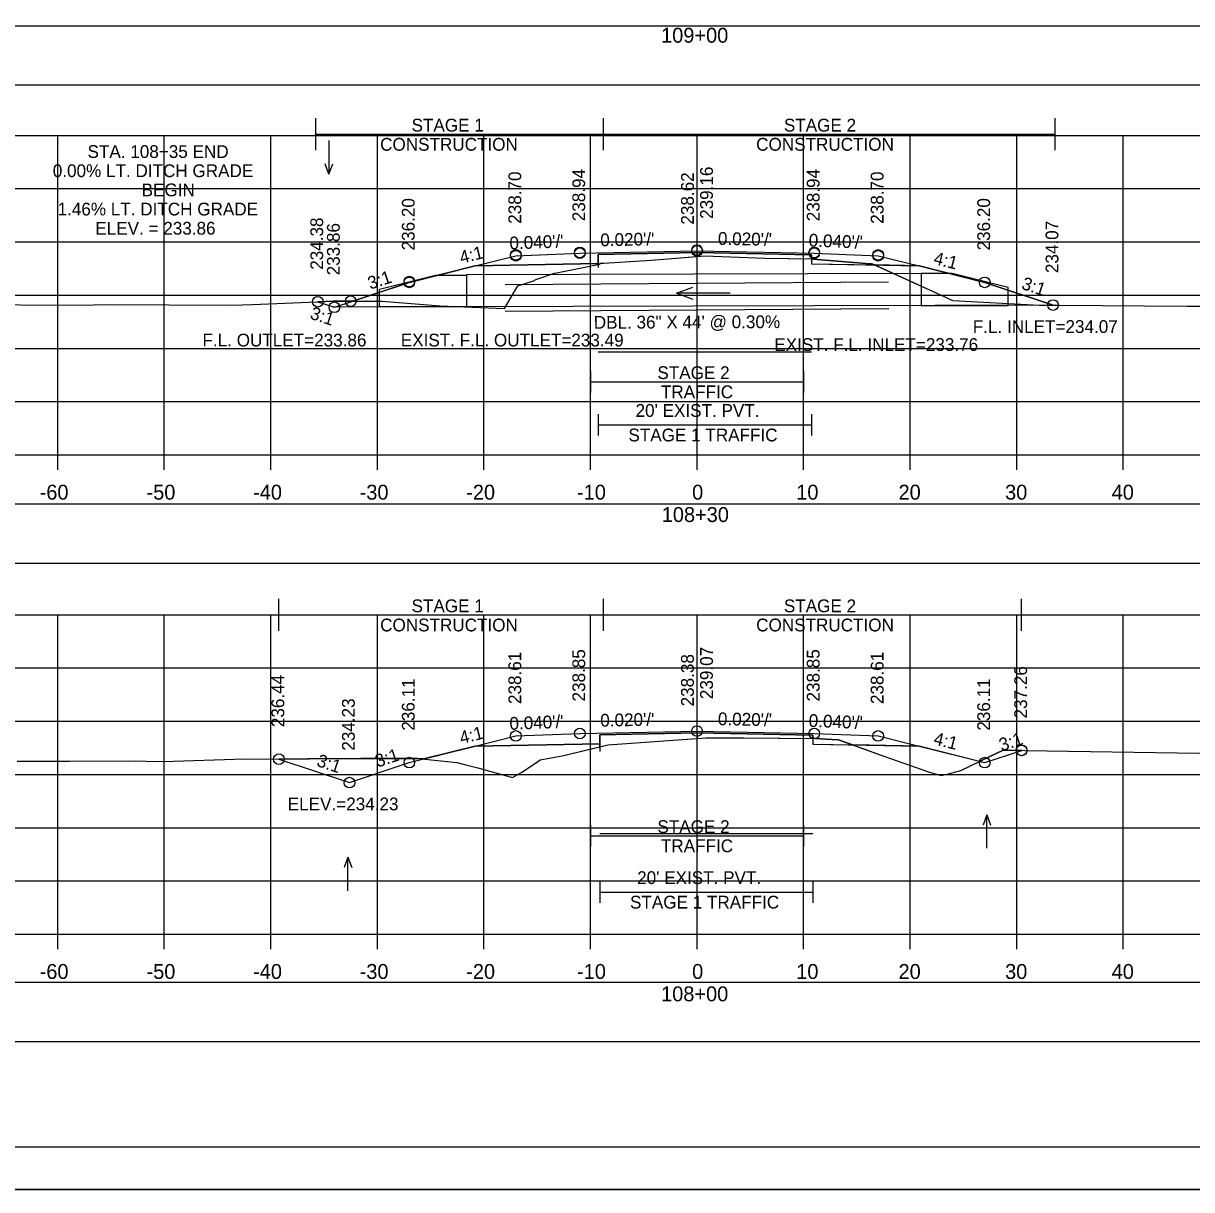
# Model space of a CAD drawing. Extents: x 1369627 to 1374022, y 380035 to 398173.
# Drawn here: x 1370116 to 1370225.7, y 380674.9 to 380784.4 of the extents above; entities that cross this region are included whole.
import ezdxf

# ---------------------------------------------------------------- set-up
doc = ezdxf.new("R2010")
doc.units = 0
for name, color, linetype in [('Default', 7, 'Continuous'), ('R_Alt Surface', 7, 'Continuous'), ('R_Axis', 7, 'Continuous'), ('R_Axis Annot', 7, 'Continuous'), ('R_Border', 7, 'Continuous'), ('R_Border Notes', 7, 'Continuous'), ('R_Exist Surface', 7, 'Continuous'), ('R_Fin Surface', 7, 'Continuous'), ('R_Grid', 7, 'Continuous'), ('R_MOT', 7, 'Continuous'), ('R_No Plot', 7, 'Continuous'), ('R_Water', 7, 'Continuous'), ('R_Water Annot', 7, 'Continuous'), ('R_Xsect Elev', 7, 'Continuous'), ('R_Xsect Slope', 7, 'Continuous'), ('T_Vehicle Path Rt', 7, 'Continuous')]:
    doc.layers.add(name, color=color, linetype=linetype)

msp = doc.modelspace()

# ---------------------------------------------------------------- linework, layer by layer
at = {"layer": 'Default'}
for points in [[(1370029.24, 380778.6), (1370329.24, 380778.6), (1370329.24, 380784.12), (1370029.24, 380784.12)], [(1370029.24, 380733.71), (1370329.24, 380733.71), (1370329.24, 380739.23), (1370029.24, 380739.23)], [(1370029.24, 380688.8), (1370329.24, 380688.8), (1370329.24, 380694.33), (1370029.24, 380694.33)]]:
    msp.add_lwpolyline(points, close=True, dxfattribs=at)
at = {"layer": 'R_Alt Surface'}
for points in [[(1370158.41, 380761.62), (1370169.97, 380761.85), (1370169.97, 380762.68), (1370179.24, 380762.87), (1370189.97, 380762.65), (1370189.97, 380761.82), (1370200.07, 380761.62)], [(1370158.41, 380716.52), (1370170.11, 380716.75), (1370170.11, 380717.59), (1370179.24, 380717.77), (1370190.11, 380717.55), (1370190.11, 380716.72), (1370200.07, 380716.52)]]:
    msp.add_lwpolyline(points, dxfattribs=at)
at = {"layer": 'R_Axis'}
for p, q in [((1370029.24, 380743.87), (1370329.24, 380743.87)), ((1370119.24, 380742.47), (1370119.24, 380743.87)), ((1370129.24, 380742.47), (1370129.24, 380743.87)), ((1370139.24, 380742.47), (1370139.24, 380743.87)), ((1370149.24, 380742.47), (1370149.24, 380743.87)), ((1370159.24, 380742.47), (1370159.24, 380743.87)), ((1370169.24, 380742.47), (1370169.24, 380743.87)), ((1370179.24, 380742.47), (1370179.24, 380743.87)), ((1370189.24, 380742.47), (1370189.24, 380743.87)), ((1370199.24, 380742.47), (1370199.24, 380743.87)), ((1370209.24, 380742.47), (1370209.24, 380743.87)), ((1370219.24, 380742.47), (1370219.24, 380743.87)), ((1370029.24, 380698.87), (1370329.24, 380698.87)), ((1370119.24, 380697.47), (1370119.24, 380698.87)), ((1370129.24, 380697.47), (1370129.24, 380698.87)), ((1370139.24, 380697.47), (1370139.24, 380698.87)), ((1370149.24, 380697.47), (1370149.24, 380698.87)), ((1370159.24, 380697.47), (1370159.24, 380698.87)), ((1370169.24, 380697.47), (1370169.24, 380698.87)), ((1370179.24, 380697.47), (1370179.24, 380698.87)), ((1370189.24, 380697.47), (1370189.24, 380698.87)), ((1370199.24, 380697.47), (1370199.24, 380698.87)), ((1370209.24, 380697.47), (1370209.24, 380698.87)), ((1370219.24, 380697.47), (1370219.24, 380698.87))]:
    msp.add_line(p, q, dxfattribs=at)
at = {"layer": 'R_Border'}
msp.add_line((1370337.42, 380678.87), (1370021.24, 380678.87), dxfattribs=at)
at = {"layer": 'R_Exist Surface'}
for points in [[(1370110.13, 380757.98), (1370121.37, 380757.94), (1370123.82, 380757.99), (1370135.59, 380757.94), (1370137.53, 380757.98), (1370145.1, 380758.31), (1370149.7, 380758.3), (1370155.13, 380757.88), (1370161.16, 380757.62), (1370162.42, 380759.73), (1370163.88, 380760.21), (1370164.11, 380760.35), (1370165.85, 380760.92), (1370165.88, 380760.93), (1370165.89, 380760.93), (1370165.9, 380760.93), (1370170.13, 380761.78), (1370170.18, 380761.87), (1370170.5, 380761.88), (1370174.95, 380762.14), (1370179.97, 380762.55), (1370185.6, 380762.35), (1370190.11, 380762.27), (1370190.12, 380762.26), (1370190.14, 380762.26), (1370195.46, 380761.82), (1370195.6, 380761.8), (1370195.74, 380761.78), (1370202.48, 380758.71), (1370203.21, 380758.38), (1370211.37, 380757.93), (1370213.26, 380757.94), (1370225.23, 380757.84), (1370226.95, 380757.83)], [(1370115.45, 380715.13), (1370120.35, 380715.13), (1370125.88, 380715.15), (1370129.14, 380715.09), (1370136.79, 380715.35), (1370139.23, 380715.3), (1370142.78, 380715.33), (1370142.81, 380715.33), (1370142.85, 380715.33), (1370147.69, 380715.36), (1370151.87, 380715.37), (1370153, 380715.38), (1370153.71, 380715.31), (1370156.7, 380714.99), (1370157.53, 380714.77), (1370158.67, 380714.48), (1370161.91, 380713.59), (1370162.8, 380714.08), (1370164.07, 380714.93), (1370164.52, 380715.24), (1370166.58, 380715.63), (1370170.87, 380716.64), (1370177.01, 380717.1), (1370180.11, 380717.32), (1370183.63, 380717.3), (1370190.4, 380717.25), (1370191.32, 380717.19), (1370192.51, 380717.13), (1370196.76, 380715.59), (1370200.96, 380714.13), (1370201.5, 380713.97), (1370202.15, 380713.76), (1370203.06, 380714), (1370204, 380714.23), (1370205.93, 380715.18), (1370207.97, 380716.16), (1370232.51, 380715.78)]]:
    msp.add_lwpolyline(points, dxfattribs=at)
at = {"layer": 'R_Fin Surface'}
for points in [[(1370143.65, 380758.25), (1370145.21, 380757.73), (1370152.24, 380760.07), (1370158.41, 380761.62), (1370162.24, 380762.57), (1370168.24, 380762.81), (1370179.24, 380763.03), (1370190.24, 380762.81), (1370196.24, 380762.57), (1370200.07, 380761.62), (1370206.24, 380760.07), (1370212.65, 380757.94)], [(1370140, 380715.31), (1370146.62, 380713.1), (1370152.24, 380714.98), (1370158.41, 380716.52), (1370162.24, 380717.48), (1370168.24, 380717.72), (1370179.24, 380717.94), (1370190.24, 380717.72), (1370196.24, 380717.48), (1370200.07, 380716.52), (1370206.24, 380714.98), (1370209.71, 380716.13)]]:
    msp.add_lwpolyline(points, dxfattribs=at)
at = {"layer": 'R_Grid'}
for p, q in [((1370029.24, 380773.87), (1370329.24, 380773.87)), ((1370119.24, 380743.87), (1370119.24, 380773.87)), ((1370129.24, 380743.87), (1370129.24, 380773.87)), ((1370139.24, 380743.87), (1370139.24, 380773.87)), ((1370149.24, 380743.87), (1370149.24, 380773.87)), ((1370159.24, 380743.87), (1370159.24, 380773.87)), ((1370169.24, 380743.87), (1370169.24, 380773.87)), ((1370179.24, 380743.87), (1370179.24, 380773.87)), ((1370189.24, 380743.87), (1370189.24, 380773.87)), ((1370199.24, 380743.87), (1370199.24, 380773.87)), ((1370209.24, 380743.87), (1370209.24, 380773.87)), ((1370219.24, 380743.87), (1370219.24, 380773.87)), ((1370029.24, 380768.87), (1370329.24, 380768.87)), ((1370029.24, 380763.87), (1370329.24, 380763.87)), ((1370029.24, 380758.87), (1370329.24, 380758.87)), ((1370029.24, 380753.87), (1370329.24, 380753.87)), ((1370029.24, 380748.87), (1370329.24, 380748.87)), ((1370029.24, 380743.87), (1370329.24, 380743.87)), ((1370029.24, 380728.87), (1370329.24, 380728.87)), ((1370119.24, 380698.87), (1370119.24, 380728.87)), ((1370129.24, 380698.87), (1370129.24, 380728.87)), ((1370139.24, 380698.87), (1370139.24, 380728.87)), ((1370149.24, 380698.87), (1370149.24, 380728.87)), ((1370159.24, 380698.87), (1370159.24, 380728.87)), ((1370169.24, 380698.87), (1370169.24, 380728.87)), ((1370179.24, 380698.87), (1370179.24, 380728.87)), ((1370189.24, 380698.87), (1370189.24, 380728.87)), ((1370199.24, 380698.87), (1370199.24, 380728.87)), ((1370209.24, 380698.87), (1370209.24, 380728.87)), ((1370219.24, 380698.87), (1370219.24, 380728.87)), ((1370029.24, 380723.87), (1370329.24, 380723.87)), ((1370029.24, 380718.87), (1370329.24, 380718.87)), ((1370029.24, 380713.87), (1370329.24, 380713.87)), ((1370029.24, 380708.87), (1370329.24, 380708.87)), ((1370029.24, 380703.87), (1370329.24, 380703.87)), ((1370029.24, 380698.87), (1370329.24, 380698.87))]:
    msp.add_line(p, q, dxfattribs=at)
at = {"layer": 'R_MOT'}
for p, q in [((1370143.47, 380772.48), (1370143.47, 380775.48)), ((1370170.47, 380772.48), (1370170.47, 380775.48)), ((1370212.86, 380772.48), (1370212.86, 380775.48)), ((1370143.47, 380773.98), (1370212.86, 380773.98)), ((1370169.24, 380751.72), (1370169.24, 380749.72)), ((1370189.24, 380751.72), (1370189.24, 380749.72)), ((1370169.24, 380750.72), (1370189.24, 380750.72)), ((1370169.97, 380747.68), (1370169.97, 380745.68)), ((1370189.97, 380747.68), (1370189.97, 380745.68)), ((1370169.97, 380746.68), (1370189.97, 380746.68)), ((1370139.99, 380727.35), (1370139.99, 380730.35)), ((1370170.47, 380727.35), (1370170.47, 380730.35)), ((1370209.69, 380727.35), (1370209.69, 380730.35)), ((1370139.99, 380728.85), (1370209.69, 380728.85)), ((1370169.24, 380709.1), (1370169.24, 380707.1)), ((1370189.24, 380709.1), (1370189.24, 380707.1)), ((1370169.24, 380708.1), (1370189.24, 380708.1)), ((1370170.11, 380703.82), (1370170.11, 380701.82)), ((1370190.11, 380703.82), (1370190.11, 380701.82)), ((1370170.11, 380702.82), (1370190.11, 380702.82))]:
    msp.add_line(p, q, dxfattribs=at)
at = {"layer": 'R_No Plot'}
msp.add_line((1370008.84, 380674.89), (1370342.17, 380674.89), dxfattribs=at)
for points in [[(1370008.83, 380888.23), (1370342.17, 380888.23), (1370342.17, 380674.89), (1370008.83, 380674.89)], [(1370255.16, 380884.33), (1370274.78, 380884.33), (1370274.78, 380874.45), (1370290.89, 380874.45), (1370314.09, 380874.45), (1370314.09, 380841.78), (1370337.3, 380841.78), (1370337.42, 380678.87), (1370021.24, 380678.87), (1370021.24, 380884.33)]]:
    msp.add_lwpolyline(points, close=True, dxfattribs=at)
for points in [[(1370169.97, 380753.55), (1370189.97, 380753.55)], [(1370170.11, 380708.32), (1370190.11, 380708.32)]]:
    msp.add_lwpolyline(points, dxfattribs=at)
for centre in [(1370168.24, 380762.88), (1370168.24, 380762.81), (1370179.24, 380763.1), (1370179.24, 380763.03), (1370190.24, 380762.88), (1370190.24, 380762.81), (1370162.24, 380762.64), (1370162.24, 380762.57), (1370196.24, 380762.64), (1370196.24, 380762.57), (1370152.24, 380760.14), (1370152.24, 380760.07), (1370206.24, 380760.07), (1370143.65, 380758.25), (1370145.21, 380757.73), (1370146.74, 380758.31), (1370212.65, 380757.94), (1370179.24, 380717.94), (1370162.24, 380717.48), (1370168.24, 380717.72), (1370190.24, 380717.72), (1370196.24, 380717.48), (1370196.24, 380717.48), (1370209.69, 380716.13), (1370209.71, 380716.13), (1370140, 380715.31), (1370152.24, 380714.98), (1370206.24, 380714.98), (1370146.62, 380713.1)]:
    msp.add_circle(centre, 0.5, dxfattribs=at)
at = {"layer": 'R_Water'}
for p, q in [((1370200.28, 380760.9), (1370157.6, 380760.77)), ((1370161.22, 380759.86), (1370197.22, 380760.13)), ((1370212.86, 380757.94), (1370145, 380757.73)), ((1370161.24, 380757.36), (1370197.24, 380757.63))]:
    msp.add_line(p, q, dxfattribs=at)
for points in [[(1370157.6, 380760.76), (1370157.6, 380757.76), (1370149.45, 380757.76), (1370149.45, 380759.43), (1370154.7, 380760.76)], [(1370200.28, 380760.91), (1370200.28, 380757.91), (1370208.43, 380757.91), (1370208.43, 380759.58), (1370203.18, 380760.91)]]:
    msp.add_lwpolyline(points, close=True, dxfattribs=at)
at = {"layer": 'R_Water Annot'}
for p, q in [((1370144.7, 380773.38), (1370144.7, 380770.24)), ((1370144.7, 380770.24), (1370144.35, 380771.2)), ((1370144.7, 380770.24), (1370145.05, 380771.2)), ((1370177.31, 380759.05), (1370178.85, 380759.61)), ((1370182.34, 380759.05), (1370177.31, 380759.05)), ((1370177.31, 380759.05), (1370178.85, 380758.49)), ((1370206.43, 380710.08), (1370206.08, 380709.12)), ((1370206.43, 380706.94), (1370206.43, 380710.08)), ((1370206.43, 380710.08), (1370206.78, 380709.12)), ((1370146.48, 380706.09), (1370146.13, 380705.13)), ((1370146.48, 380702.95), (1370146.48, 380706.09)), ((1370146.48, 380706.09), (1370146.83, 380705.13))]:
    msp.add_line(p, q, dxfattribs=at)
at = {"layer": 'R_Xsect Elev'}
for p, q in [((1370179.24, 380762.49), (1370179.24, 380772.49)), ((1370179.24, 380717.26), (1370179.24, 380727.26))]:
    msp.add_line(p, q, dxfattribs=at)
at = {"layer": 'T_Vehicle Path Rt'}
for p, q in [((1370179.24, 380762.49), (1370179.24, 380762.87)), ((1370189.97, 380762.65), (1370179.24, 380762.87)), ((1370179.24, 380762.87), (1370179.24, 380762.49)), ((1370189.97, 380762.27), (1370189.97, 380762.65)), ((1370189.97, 380762.27), (1370189.97, 380761.82)), ((1370169.97, 380761.85), (1370158.41, 380761.62)), ((1370169.97, 380761.85), (1370169.97, 380761.45)), ((1370169.97, 380761.75), (1370169.97, 380761.85)), ((1370169.97, 380761.85), (1370169.97, 380761.75)), ((1370189.97, 380761.82), (1370195.92, 380761.7)), ((1370200.07, 380761.62), (1370195.92, 380761.7)), ((1370195.92, 380761.7), (1370202.48, 380758.71)), ((1370145.1, 380758.31), (1370143.65, 380758.25)), ((1370146.94, 380758.31), (1370145.1, 380758.31)), ((1370190.11, 380717.55), (1370179.24, 380717.77)), ((1370179.24, 380717.77), (1370179.24, 380717.26)), ((1370179.24, 380717.26), (1370179.24, 380717.77)), ((1370190.11, 380717.26), (1370190.11, 380717.55)), ((1370158.41, 380716.52), (1370153.61, 380715.32)), ((1370170.11, 380716.75), (1370158.41, 380716.52)), ((1370170.11, 380716.75), (1370170.11, 380716.01)), ((1370170.11, 380716.46), (1370170.11, 380716.75)), ((1370170.11, 380716.75), (1370170.11, 380716.46)), ((1370170.11, 380716.46), (1370170.87, 380716.64)), ((1370190.24, 380716.72), (1370193.83, 380716.65)), ((1370200.07, 380716.52), (1370193.86, 380716.64)), ((1370205.76, 380715.1), (1370200.07, 380716.52)), ((1370206.24, 380714.98), (1370209.71, 380716.13)), ((1370153.59, 380715.32), (1370153, 380715.38)), ((1370205.76, 380715.1), (1370206.24, 380714.98))]:
    msp.add_line(p, q, dxfattribs=at)
for points in [[(1370179.24, 380762.87), (1370169.97, 380762.68), (1370169.97, 380761.85)], [(1370169.97, 380761.75), (1370170.13, 380761.78), (1370170.18, 380761.87), (1370170.5, 380761.88), (1370174.95, 380762.14), (1370179.24, 380762.49)], [(1370179.24, 380762.49), (1370179.97, 380762.55), (1370185.6, 380762.35), (1370189.97, 380762.27)], [(1370195.92, 380761.7), (1370195.74, 380761.78), (1370195.6, 380761.8), (1370195.46, 380761.82), (1370190.14, 380762.26), (1370190.12, 380762.26), (1370190.11, 380762.27), (1370189.97, 380762.27)], [(1370146.94, 380758.31), (1370149.7, 380758.3), (1370155.13, 380757.88), (1370161.16, 380757.62), (1370162.42, 380759.73), (1370163.88, 380760.21), (1370164.11, 380760.35), (1370165.85, 380760.92), (1370165.88, 380760.93), (1370165.9, 380760.93), (1370169.97, 380761.75)], [(1370158.41, 380761.62), (1370152.24, 380760.07), (1370146.94, 380758.31)], [(1370212.65, 380757.94), (1370206.24, 380760.07), (1370200.07, 380761.62)], [(1370143.65, 380758.25), (1370145.21, 380757.73), (1370146.94, 380758.31)], [(1370202.48, 380758.71), (1370203.21, 380758.38), (1370211.37, 380757.93), (1370212.65, 380757.94)], [(1370179.24, 380717.77), (1370170.11, 380717.59), (1370170.11, 380716.75)], [(1370170.87, 380716.64), (1370177.01, 380717.1), (1370179.24, 380717.26)], [(1370179.24, 380717.26), (1370180.11, 380717.32), (1370183.63, 380717.3), (1370190.11, 380717.26)], [(1370190.24, 380717.26), (1370190.11, 380717.26), (1370190.11, 380716.72), (1370190.24, 380716.72)], [(1370193.83, 380716.65), (1370192.51, 380717.13), (1370191.32, 380717.19), (1370190.4, 380717.25), (1370190.24, 380717.26)], [(1370153.61, 380715.32), (1370153.71, 380715.31), (1370156.7, 380714.99), (1370157.53, 380714.77), (1370158.67, 380714.48), (1370161.91, 380713.59), (1370162.8, 380714.08), (1370164.07, 380714.93), (1370164.52, 380715.24), (1370166.58, 380715.63), (1370170.11, 380716.46)], [(1370193.86, 380716.64), (1370196.76, 380715.59), (1370200.96, 380714.13), (1370201.5, 380713.97), (1370202.15, 380713.76), (1370203.06, 380714), (1370204, 380714.23), (1370205.76, 380715.1)], [(1370209.71, 380716.13), (1370207.97, 380716.16), (1370205.93, 380715.18), (1370205.76, 380715.1)], [(1370153, 380715.38), (1370151.87, 380715.37), (1370147.69, 380715.36), (1370142.85, 380715.33), (1370142.81, 380715.33), (1370142.78, 380715.33), (1370140, 380715.31)], [(1370140, 380715.31), (1370146.62, 380713.1), (1370152.24, 380714.98), (1370153.6, 380715.32)], [(1370153.6, 380715.32), (1370153.59, 380715.32)], [(1370205.76, 380715.1), (1370205.76, 380715.1)]]:
    msp.add_lwpolyline(points, dxfattribs=at)

# ---------------------------------------------------------------- texts
at = {"layer": 'R_Axis Annot'}
for s, height, p in [('109+00', 1.4, (1370175.87, 380782.57)), ("20' EXIST. PVT.", 1.2, (1370173.47, 380747.44)), ('-60', 1.4, (1370117.55, 380739.67)), ('-50', 1.4, (1370127.58, 380739.67)), ('-40', 1.4, (1370137.58, 380739.67)), ('-30', 1.4, (1370147.58, 380739.67)), ('-20', 1.4, (1370157.58, 380739.67)), ('-10', 1.4, (1370167.98, 380739.67)), ('0', 1.4, (1370178.78, 380739.67)), ('10', 1.4, (1370188.55, 380739.67)), ('20', 1.4, (1370198.15, 380739.67)), ('30', 1.4, (1370208.15, 380739.67)), ('40', 1.4, (1370218.15, 380739.67)), ('108+30', 1.4, (1370175.93, 380737.57)), ("20' EXIST. PVT.", 1.2, (1370173.62, 380703.58)), ('-60', 1.4, (1370117.55, 380694.67)), ('-50', 1.4, (1370127.58, 380694.67)), ('-40', 1.4, (1370137.58, 380694.67)), ('-30', 1.4, (1370147.58, 380694.67)), ('-20', 1.4, (1370157.58, 380694.67)), ('-10', 1.4, (1370167.98, 380694.67)), ('0', 1.4, (1370178.78, 380694.67)), ('10', 1.4, (1370188.55, 380694.67)), ('20', 1.4, (1370198.15, 380694.67)), ('30', 1.4, (1370208.15, 380694.67)), ('40', 1.4, (1370218.15, 380694.67)), ('108+00', 1.4, (1370175.87, 380692.57))]:
    msp.add_text(s, height=height, dxfattribs=at).set_placement(p)
at = {"layer": 'R_Border Notes'}
for s, p in [('F.L. INLET=234.07', (1370205.12, 380755.32)), ('F.L. OUTLET=233.86', (1370132.83, 380754.05)), ('EXIST. F.L. OUTLET=233.49', (1370151.44, 380754.05)), ('EXIST. F.L. INLET=233.76', (1370186.49, 380753.63)), ('ELEV.=234.23', (1370140.83, 380710.5))]:
    msp.add_text(s, height=1.2, dxfattribs=at).set_placement(p)
at = {"layer": 'R_MOT'}
for s, p in [('STAGE 1', (1370152.45, 380774.23)), ('STAGE 2', (1370187.39, 380774.23)), ('CONSTRUCTION', (1370149.5, 380772.43)), ('CONSTRUCTION', (1370184.79, 380772.43)), ('STAGE 2', (1370175.52, 380750.99)), ('TRAFFIC', (1370175.85, 380749.19)), ('STAGE 1 TRAFFIC', (1370172.8, 380745.14)), ('STAGE 1', (1370152.45, 380729.1)), ('STAGE 2', (1370187.39, 380729.1)), ('CONSTRUCTION', (1370149.5, 380727.3)), ('CONSTRUCTION', (1370184.79, 380727.3)), ('STAGE 2', (1370175.52, 380708.37)), ('TRAFFIC', (1370175.85, 380706.57)), ('STAGE 1 TRAFFIC', (1370172.95, 380701.28))]:
    msp.add_text(s, height=1.2, dxfattribs=at).set_placement(p)
at = {"layer": 'R_Water Annot'}
msp.add_text('DBL. 36" X 44\' @ 0.30%', height=1.2, rotation=0.1754, dxfattribs=at).set_placement((1370169.55, 380755.72))
at = {"layer": 'R_Xsect Elev'}
for s, p in [('STA. 108+35 END', (1370122.04, 380771.75)), ('0.00% LT. DITCH GRADE', (1370118.78, 380769.95)), ('BEGIN', (1370127.12, 380768.15)), ('1.46% LT. DITCH GRADE', (1370119.23, 380766.35)), ('ELEV. = 233.86', (1370122.77, 380764.55))]:
    msp.add_text(s, height=1.2, dxfattribs=at).set_placement(p)
for s, p in [('238.70', (1370162.74, 380765.57)), ('238.94', (1370168.74, 380765.81)), ('238.62', (1370178.94, 380765.49)), ('239.16', (1370180.73, 380766.03)), ('238.94', (1370190.74, 380765.81)), ('238.70', (1370196.74, 380765.57)), ('236.20', (1370152.74, 380763.07)), ('236.20', (1370206.74, 380763.07)), ('234.38', (1370144.15, 380761.25)), ('233.86', (1370145.71, 380760.73)), ('234.07', (1370213.15, 380760.94)), ('238.61', (1370162.74, 380720.48)), ('238.85', (1370168.74, 380720.72)), ('238.38', (1370178.94, 380720.26)), ('239.07', (1370180.73, 380720.94)), ('238.85', (1370190.74, 380720.72)), ('238.61', (1370196.74, 380720.48)), ('237.26', (1370210.21, 380719.13)), ('236.44', (1370140.5, 380718.31)), ('236.11', (1370152.74, 380717.98)), ('236.11', (1370206.74, 380717.98)), ('234.23', (1370147.12, 380716.1))]:
    msp.add_text(s, height=1.2, rotation=90, dxfattribs=at).set_placement(p)
at = {"layer": 'R_Xsect Slope'}
for s, rotation, p in [("0.040'/'", 2.2906, (1370161.66, 380763.15)), ("0.020'/'", 1.1458, (1370170.17, 380763.45)), ("0.020'/'", 358.8542, (1370181.19, 380763.6)), ("0.040'/'", 357.7094, (1370189.7, 380763.44)), ('4:1', 14.0362, (1370157.12, 380761.81)), ('4:1', 345.9638, (1370201.36, 380761.81)), ('3:1', 18.4349, (1370148.57, 380759.38)), ('3:1', 341.5651, (1370209.61, 380759.48)), ('3:1', 341.5651, (1370142.84, 380756.69)), ("0.040'/'", 2.2906, (1370161.66, 380718.05)), ("0.020'/'", 1.1458, (1370170.17, 380718.35)), ("0.020'/'", 358.8542, (1370181.19, 380718.5)), ("0.040'/'", 357.7094, (1370189.7, 380718.34)), ('4:1', 14.0362, (1370157.12, 380716.71)), ('4:1', 345.9638, (1370201.36, 380716.71)), ('3:1', 18.4349, (1370207.82, 380716.03)), ('3:1', 18.4349, (1370149.27, 380714.51)), ('3:1', 341.5651, (1370143.47, 380714.68))]:
    msp.add_text(s, height=1.2, rotation=rotation, dxfattribs=at).set_placement(p)

doc.saveas('drawing.dxf')
